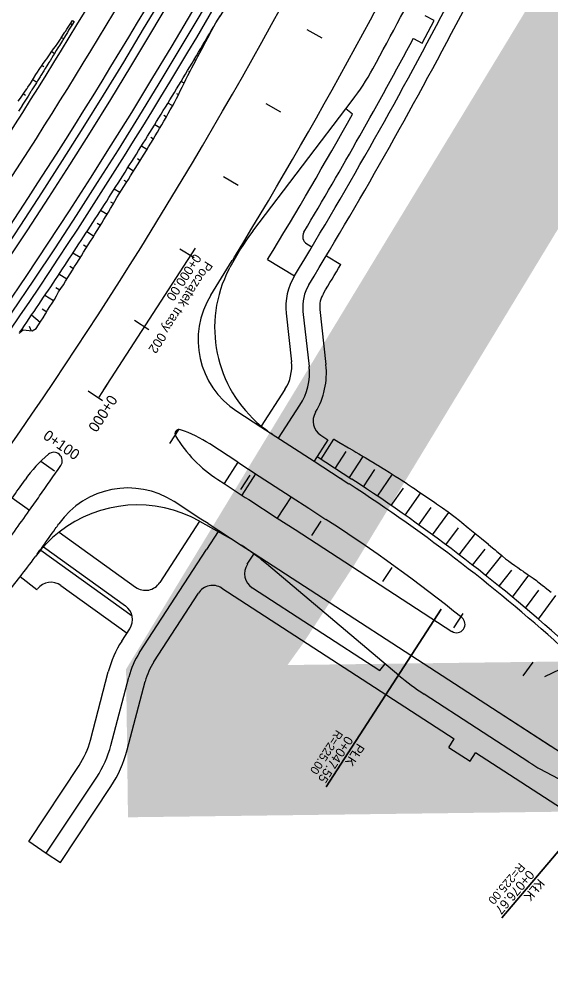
# Model space of a CAD drawing. Extents: x 6503541 to 6503743, y 5888004 to 5888145.
# Drawn here: x 6503687.09 to 6503688.597, y 5888085.781 to 5888088.473 of the extents above; entities that cross this region are included whole.
import ezdxf

# ---------------------------------------------------------------- set-up
doc = ezdxf.new("R2010")
doc.units = 0
doc.layers.add('12', color=7, linetype='Continuous')

msp = doc.modelspace()

# ---------------------------------------------------------------- linework, layer by layer
at = {"layer": '12'}
for p, q in [((6503688.2665, 5888088.4688), (6503688.2411, 5888088.4823)), ((6503687.6414, 5888088.4512), (6503687.6415, 5888088.4512)), ((6503687.648, 5888088.4625), (6503687.6478, 5888088.4626)), ((6503688.2327, 5888088.4052), (6503688.2665, 5888088.4688)), ((6503687.6243, 5888088.4195), (6503687.6229, 5888088.4203)), ((6503688.2073, 5888088.4187), (6503688.2327, 5888088.4052)), ((6503687.606, 5888088.3885), (6503687.6074, 5888088.3878)), ((6503687.5904, 5888088.356), (6503687.5861, 5888088.3583)), ((6503687.5707, 5888088.3257), (6503687.5739, 5888088.3241)), ((6503687.5578, 5888088.2918), (6503687.5489, 5888088.2963)), ((6503687.536, 5888088.2625), (6503687.5417, 5888088.2596)), ((6503687.9847, 5888088.2862), (6503687.9847, 5888088.2862)), ((6503687.5253, 5888088.2276), (6503687.5117, 5888088.235)), ((6503687.7524, 5888087.8721), (6503688.0339, 5888088.2422)), ((6503688.0352, 5888088.2042), (6503688.0161, 5888088.2187)), ((6503687.5002, 5888088.2005), (6503687.5074, 5888088.1964)), ((6503687.4893, 5888088.1652), (6503687.4743, 5888088.174)), ((6503687.4632, 5888088.1389), (6503687.4709, 5888088.1343)), ((6503687.4522, 5888088.1035), (6503687.4365, 5888088.1131)), ((6503687.4255, 5888088.0777), (6503687.4335, 5888088.0728)), ((6503687.4144, 5888088.0423), (6503687.3984, 5888088.0523)), ((6503687.3872, 5888088.0169), (6503687.3951, 5888088.0118)), ((6503687.3759, 5888087.9814), (6503687.3598, 5888087.9914)), ((6503687.3487, 5888087.9557), (6503687.3572, 5888087.9506)), ((6503687.3392, 5888087.9195), (6503687.3209, 5888087.9305)), ((6503687.3109, 5888087.8947), (6503687.3203, 5888087.8889)), ((6503687.3013, 5888087.8583), (6503687.2819, 5888087.8703)), ((6503687.2723, 5888087.8339), (6503687.2823, 5888087.8277)), ((6503687.9052, 5888087.8365), (6503687.92, 5888087.8275)), ((6503687.2632, 5888087.7972), (6503687.2426, 5888087.8101)), ((6503687.7943, 5888087.7915), (6503687.8702, 5888087.7454)), ((6503687.9608, 5888087.8027), (6503688.0018, 5888087.7778)), ((6503687.2254, 5888087.7359), (6503687.203, 5888087.7501)), ((6503687.2334, 5888087.7733), (6503687.2442, 5888087.7666)), ((6503687.6851, 5888087.7653), (6503687.6873, 5888087.7695)), ((6503687.1943, 5888087.7129), (6503687.2057, 5888087.7058)), ((6503687.1876, 5888087.6747), (6503687.1627, 5888087.6897)), ((6503687.1557, 5888087.6521), (6503687.1687, 5888087.6441)), ((6503687.8945, 5888087.645), (6503687.9119, 5888087.4887)), ((6503687.9422, 5888087.6503), (6503687.9596, 5888087.494)), ((6503687.1498, 5888087.6135), (6503687.1251, 5888087.6339)), ((6503687.8468, 5888087.6397), (6503687.8621, 5888087.5022)), ((6503687.1184, 5888087.6026), (6503687.1245, 5888087.5902)), ((6503687.0905, 5888087.583), (6503687.0908, 5888087.5827)), ((6503687.0918, 5888087.5846), (6503687.0917, 5888087.5848)), ((6503687.8435, 5888087.4237), (6503687.7763, 5888087.32)), ((6503687.8254, 5888087.2855), (6503687.8859, 5888087.3788)), ((6503687.7067, 5888087.3625), (6503687.7751, 5888087.3182)), ((6503687.7751, 5888087.3182), (6503687.9261, 5888087.2202)), ((6503687.945, 5888087.2938), (6503687.9653, 5888087.2807)), ((6503687.7098, 5888087.2175), (6503687.6302, 5888087.2691)), ((6503687.9653, 5888087.2807), (6503687.9261, 5888087.2202)), ((6503687.7098, 5888087.2175), (6503687.6707, 5888087.1571)), ((6503687.7098, 5888087.2175), (6503687.7702, 5888087.1783)), ((6503687.9261, 5888087.2202), (6503688.0249, 5888087.1562)), ((6503687.9346, 5888087.2333), (6503688.0334, 5888087.1693)), ((6503687.6533, 5888087.1683), (6503687.6707, 5888087.1571)), ((6503687.7702, 5888087.1783), (6503687.8609, 5888087.1196)), ((6503687.9969, 5888087.1744), (6503688.0015, 5888087.1714)), ((6503687.6707, 5888087.1571), (6503687.7311, 5888087.1179)), ((6503687.1192, 5888087.0803), (6503687.0703, 5888087.1155)), ((6503687.6054, 5888087.0563), (6503687.5292, 5888087.1058)), ((6503687.7311, 5888087.1179), (6503687.7411, 5888087.1114)), ((6503687.7411, 5888087.1114), (6503687.8217, 5888087.0591)), ((6503687.8609, 5888087.1196), (6503687.8217, 5888087.0591)), ((6503687.8609, 5888087.1196), (6503687.9112, 5888087.0869)), ((6503687.9112, 5888087.0869), (6503687.9596, 5888087.0555)), ((6503687.6013, 5888087.0508), (6503687.6914, 5888087.0006)), ((6503687.6254, 5888087.0434), (6503687.6054, 5888087.0563)), ((6503687.8217, 5888087.0591), (6503687.872, 5888087.0265)), ((6503687.6254, 5888087.0434), (6503687.7193, 5888086.9825)), ((6503687.872, 5888087.0265), (6503688.3166, 5888086.7382)), ((6503687.2037, 5888087.0195), (6503687.4203, 5888086.8635)), ((6503687.1589, 5888086.9778), (6503687.3915, 5888086.8104)), ((6503687.4316, 5888086.6781), (6503687.6207, 5888086.9698)), ((6503687.7194, 5888086.9825), (6503687.7565, 5888086.9584)), ((6503687.1519, 5888086.968), (6503687.4102, 5888086.7821)), ((6503687.7368, 5888086.9282), (6503687.7557, 5888086.9573)), ((6503687.7565, 5888086.9584), (6503688.4316, 5888086.5207)), ((6503688.1664, 5888086.6134), (6503687.7913, 5888086.9292)), ((6503687.1401, 5888086.8555), (6503687.0928, 5888086.8923)), ((6503687.2085, 5888086.8682), (6503687.3959, 5888086.7333)), ((6503687.751, 5888086.8619), (6503688.1123, 5888086.6276)), ((6503687.4719, 5888086.652), (6503687.5981, 5888086.8466)), ((6503687.6645, 5888086.8607), (6503688.3234, 5888086.4335)), ((6503687.3813, 5888086.7108), (6503687.4037, 5888086.7453)), ((6503688.1123, 5888086.6276), (6503688.1278, 5888086.6459)), ((6503687.2921, 5888086.43), (6503687.3428, 5888086.6236)), ((6503687.3501, 5888086.4148), (6503687.4009, 5888086.6084)), ((6503687.3966, 5888086.4026), (6503687.4473, 5888086.5962)), ((6503688.5345, 5888086.3678), (6503688.238, 5888086.5604)), ((6503688.4316, 5888086.5207), (6503688.5962, 5888086.414)), ((6503688.4316, 5888086.5207), (6503688.8048, 5888086.2787)), ((6503688.3078, 5888086.4094), (6503688.3234, 5888086.4335)), ((6503688.3078, 5888086.4094), (6503688.3681, 5888086.3702)), ((6503688.3681, 5888086.3702), (6503688.3837, 5888086.3942)), ((6503688.8019, 5888086.1227), (6503688.3837, 5888086.3942)), ((6503687.1172, 5888086.1428), (6503687.26, 5888086.3582)), ((6503687.1672, 5888086.1096), (6503687.31, 5888086.3251)), ((6503687.2072, 5888086.0831), (6503687.35, 5888086.2986)), ((6503687.1175, 5888086.1432), (6503687.1672, 5888086.1096)), ((6503687.1672, 5888086.1096), (6503687.2072, 5888086.0831))]:
    msp.add_line(p, q, dxfattribs=at)
for points in [[(6503687.648, 5888088.4625), (6503687.6546, 5888088.4727), (6503687.6612, 5888088.4828), (6503687.6677, 5888088.493), (6503687.6743, 5888088.5032), (6503687.6808, 5888088.5134), (6503687.687, 5888088.5238), (6503687.693, 5888088.5342), (6503687.6991, 5888088.5447), (6503687.7052, 5888088.5551), (6503687.7112, 5888088.5656), (6503687.717, 5888088.5762), (6503687.7226, 5888088.5869), (6503687.7283, 5888088.5976), (6503687.7339, 5888088.6083), (6503687.7395, 5888088.6191), (6503687.745, 5888088.6298), (6503687.7506, 5888088.6405)], [(6503687.0916, 5888087.5847), (6503687.0984, 5888087.5947), (6503687.1053, 5888087.6047), (6503687.112, 5888087.6147), (6503687.1188, 5888087.6247), (6503687.1256, 5888087.6347), (6503687.1324, 5888087.6447), (6503687.1392, 5888087.6547), (6503687.1459, 5888087.6647), (6503687.1527, 5888087.6748), (6503687.1594, 5888087.6848), (6503687.1661, 5888087.6948), (6503687.1729, 5888087.7049), (6503687.1796, 5888087.7149), (6503687.1863, 5888087.725), (6503687.193, 5888087.735), (6503687.1997, 5888087.7451), (6503687.2064, 5888087.7552), (6503687.213, 5888087.7653), (6503687.2197, 5888087.7753), (6503687.2264, 5888087.7854), (6503687.233, 5888087.7955), (6503687.2397, 5888087.8056), (6503687.2463, 5888087.8157), (6503687.2529, 5888087.8258), (6503687.2595, 5888087.8359), (6503687.2661, 5888087.8461), (6503687.2727, 5888087.8562), (6503687.2793, 5888087.8663), (6503687.2859, 5888087.8764), (6503687.2925, 5888087.8866), (6503687.2991, 5888087.8967), (6503687.3056, 5888087.9069), (6503687.3122, 5888087.917), (6503687.3187, 5888087.9272), (6503687.3253, 5888087.9374), (6503687.3318, 5888087.9475), (6503687.3383, 5888087.9577), (6503687.3448, 5888087.9679), (6503687.3514, 5888087.9781), (6503687.3579, 5888087.9883), (6503687.3643, 5888087.9985), (6503687.3708, 5888088.0087), (6503687.3773, 5888088.0189), (6503687.3838, 5888088.0291), (6503687.3902, 5888088.0393), (6503687.3967, 5888088.0495), (6503687.4031, 5888088.0598), (6503687.4095, 5888088.07), (6503687.416, 5888088.0802), (6503687.4224, 5888088.0905), (6503687.4288, 5888088.1007), (6503687.4352, 5888088.111), (6503687.4416, 5888088.1212), (6503687.448, 5888088.1315), (6503687.4543, 5888088.1418), (6503687.4607, 5888088.152), (6503687.4671, 5888088.1623), (6503687.4734, 5888088.1726), (6503687.4797, 5888088.1829), (6503687.4861, 5888088.1932), (6503687.4924, 5888088.2035), (6503687.4987, 5888088.2138), (6503687.505, 5888088.2241), (6503687.5113, 5888088.2344), (6503687.5176, 5888088.2447), (6503687.5239, 5888088.2551), (6503687.5302, 5888088.2654), (6503687.5365, 5888088.2757), (6503687.5427, 5888088.2861), (6503687.549, 5888088.2964), (6503687.5552, 5888088.3068), (6503687.5614, 5888088.3171), (6503687.5677, 5888088.3275), (6503687.5739, 5888088.3378), (6503687.5801, 5888088.3482), (6503687.5863, 5888088.3586), (6503687.5925, 5888088.369), (6503687.5987, 5888088.3794), (6503687.6048, 5888088.3897), (6503687.611, 5888088.4001), (6503687.6172, 5888088.4105), (6503687.6233, 5888088.4209), (6503687.6295, 5888088.4314), (6503687.6356, 5888088.4418), (6503687.6417, 5888088.4522), (6503687.6478, 5888088.4626), (6503687.654, 5888088.473), (6503687.6601, 5888088.4835)], [(6503687.0876, 5888088.2405), (6503687.0936, 5888088.2489), (6503687.1012, 5888088.2601), (6503687.1031, 5888088.2629), (6503687.1118, 5888088.2757), (6503687.1125, 5888088.2768), (6503687.1146, 5888088.2799), (6503687.1219, 5888088.2908), (6503687.1276, 5888088.3), (6503687.1307, 5888088.3052), (6503687.1377, 5888088.3164), (6503687.1397, 5888088.3193), (6503687.1403, 5888088.3202), (6503687.1492, 5888088.3333), (6503687.1537, 5888088.34), (6503687.1587, 5888088.3472), (6503687.1651, 5888088.3562), (6503687.1675, 5888088.3596), (6503687.1684, 5888088.361), (6503687.1782, 5888088.3747), (6503687.1813, 5888088.3791), (6503687.1879, 5888088.3885), (6503687.193, 5888088.3957), (6503687.1951, 5888088.3987), (6503687.1976, 5888088.4023), (6503687.2071, 5888088.4163), (6503687.2085, 5888088.4185), (6503687.2163, 5888088.4304), (6503687.2199, 5888088.4358), (6503687.2216, 5888088.4385), (6503687.2254, 5888088.4445), (6503687.2344, 5888088.4586), (6503687.2345, 5888088.4587), (6503687.2412, 5888088.4692)], [(6503687.2457, 5888088.4665), (6503687.2393, 5888088.4559), (6503687.2392, 5888088.4557), (6503687.2305, 5888088.4414), (6503687.2268, 5888088.4353), (6503687.2251, 5888088.4326), (6503687.2218, 5888088.4271), (6503687.2143, 5888088.4149), (6503687.213, 5888088.4127), (6503687.2042, 5888088.3983), (6503687.2019, 5888088.3945), (6503687.2, 5888088.3914), (6503687.1954, 5888088.3839), (6503687.1894, 5888088.3741), (6503687.1866, 5888088.3696), (6503687.1777, 5888088.3552), (6503687.1768, 5888088.3538), (6503687.1747, 5888088.3503), (6503687.1689, 5888088.3409), (6503687.1643, 5888088.3334), (6503687.16, 5888088.3266), (6503687.1517, 5888088.3131), (6503687.1511, 5888088.3123), (6503687.1493, 5888088.3092), (6503687.1422, 5888088.2979), (6503687.139, 5888088.2928), (6503687.1333, 5888088.2837), (6503687.1264, 5888088.2726), (6503687.1244, 5888088.2694), (6503687.1237, 5888088.2683), (6503687.1154, 5888088.2551), (6503687.1137, 5888088.2523), (6503687.1065, 5888088.2408), (6503687.1009, 5888088.2321), (6503687.098, 5888088.2274), (6503687.0975, 5888088.2266), (6503687.0885, 5888088.2123)], [(6503687.0918, 5888087.5846), (6503687.1011, 5888087.5929), (6503687.1269, 5888087.59), (6503687.1385, 5888087.5967), (6503687.1453, 5888087.6068), (6503687.152, 5888087.6168), (6503687.1585, 5888087.6271), (6503687.1647, 5888087.6375), (6503687.1709, 5888087.6479), (6503687.1772, 5888087.6583), (6503687.1837, 5888087.6685), (6503687.1901, 5888087.6788), (6503687.196, 5888087.6894), (6503687.2017, 5888087.7001), (6503687.2087, 5888087.71), (6503687.2156, 5888087.72), (6503687.2219, 5888087.7303), (6503687.2283, 5888087.7406), (6503687.2346, 5888087.751), (6503687.2409, 5888087.7613), (6503687.2472, 5888087.7717), (6503687.2536, 5888087.7819), (6503687.2601, 5888087.7922), (6503687.2665, 5888087.8024), (6503687.273, 5888087.8127), (6503687.2794, 5888087.823), (6503687.2858, 5888087.8332), (6503687.2922, 5888087.8435), (6503687.2986, 5888087.8538), (6503687.305, 5888087.8641), (6503687.3113, 5888087.8744), (6503687.3177, 5888087.8847), (6503687.3241, 5888087.895), (6503687.3304, 5888087.9053), (6503687.3367, 5888087.9156), (6503687.3432, 5888087.9259), (6503687.3495, 5888087.9362), (6503687.3552, 5888087.9469), (6503687.361, 5888087.9576), (6503687.3673, 5888087.9679), (6503687.3738, 5888087.9781), (6503687.3803, 5888087.9883), (6503687.3867, 5888087.9986), (6503687.3932, 5888088.0088), (6503687.3997, 5888088.019), (6503687.4062, 5888088.0292), (6503687.4126, 5888088.0395), (6503687.4191, 5888088.0497), (6503687.4255, 5888088.0599), (6503687.4319, 5888088.0702), (6503687.4383, 5888088.0805), (6503687.4446, 5888088.0909), (6503687.4508, 5888088.1012), (6503687.4571, 5888088.1115), (6503687.4634, 5888088.1219), (6503687.4697, 5888088.1322), (6503687.476, 5888088.1426), (6503687.4822, 5888088.1529), (6503687.4883, 5888088.1634), (6503687.4944, 5888088.1739), (6503687.5004, 5888088.1844), (6503687.5065, 5888088.1948), (6503687.5125, 5888088.2053), (6503687.5186, 5888088.2158), (6503687.5246, 5888088.2263), (6503687.5304, 5888088.237), (6503687.5358, 5888088.2478), (6503687.5413, 5888088.2587), (6503687.5467, 5888088.2695), (6503687.5521, 5888088.2804), (6503687.5575, 5888088.2912), (6503687.5629, 5888088.3021), (6503687.5684, 5888088.313), (6503687.5737, 5888088.3238), (6503687.5791, 5888088.3347), (6503687.5848, 5888088.3454), (6503687.5905, 5888088.3561), (6503687.5962, 5888088.3668), (6503687.6019, 5888088.3774), (6503687.6076, 5888088.3881), (6503687.6133, 5888088.3988), (6503687.619, 5888088.4095), (6503687.6246, 5888088.4202), (6503687.6303, 5888088.4309), (6503687.6361, 5888088.4415), (6503687.642, 5888088.452), (6503687.648, 5888088.4625)], [(6503687.236, 5888088.461), (6503687.2406, 5888088.4582)], [(6503687.2412, 5888088.4692), (6503687.2457, 5888088.4665)], [(6503687.9486, 5888088.4196), (6503687.9065, 5888088.4426)], [(6503687.2099, 5888088.4207), (6503687.2128, 5888088.4189)], [(6503687.1827, 5888088.3811), (6503687.1906, 5888088.3762)], [(6503687.155, 5888088.3418), (6503687.1602, 5888088.3386)], [(6503687.1286, 5888088.3018), (6503687.1401, 5888088.2946)], [(6503687.1023, 5888088.2617), (6503687.1085, 5888088.2578)], [(6503687.8315, 5888088.2097), (6503687.7898, 5888088.2334)], [(6503687.7106, 5888088.0018), (6503687.6694, 5888088.0263)], [(6503687.3288, 5888087.4216), (6503687.4593, 5888087.623), (6503687.5899, 5888087.8244)], [(6503687.5861, 5888087.7962), (6503687.5452, 5888087.8214)], [(6503687.4579, 5888087.5928), (6503687.4175, 5888087.6187)], [(6503687.3418, 5888087.4417), (6503687.3157, 5888087.4015)], [(6503687.326, 5888087.3917), (6503687.2861, 5888087.4184)], [(6503687.5171, 5888087.2709), (6503687.5432, 5888087.3112)], [(6503687.9459, 5888087.226), (6503687.9823, 5888087.2827)], [(6503687.9823, 5888087.2827), (6503687.9827, 5888087.2831), (6503687.9841, 5888087.2823), (6503688.0012, 5888087.2718), (6503688.0032, 5888087.2706), (6503688.0184, 5888087.2613), (6503688.0237, 5888087.2582), (6503688.0358, 5888087.2512), (6503688.0445, 5888087.2461), (6503688.0532, 5888087.2411), (6503688.0652, 5888087.234), (6503688.0705, 5888087.2308), (6503688.0858, 5888087.2217), (6503688.0878, 5888087.2205), (6503688.105, 5888087.2101), (6503688.1064, 5888087.2092), (6503688.1221, 5888087.1996), (6503688.1268, 5888087.1967), (6503688.1392, 5888087.189), (6503688.1472, 5888087.184), (6503688.1562, 5888087.1783), (6503688.1674, 5888087.171), (6503688.1731, 5888087.1673), (6503688.1875, 5888087.1579), (6503688.1899, 5888087.1563), (6503688.2066, 5888087.1451), (6503688.2075, 5888087.1446), (6503688.2233, 5888087.1339), (6503688.2273, 5888087.1311), (6503688.2399, 5888087.1225), (6503688.2471, 5888087.1175), (6503688.2565, 5888087.1111), (6503688.267, 5888087.104), (6503688.2731, 5888087.0998), (6503688.2867, 5888087.0904), (6503688.2896, 5888087.0884), (6503688.3061, 5888087.0768), (6503688.3064, 5888087.0766), (6503688.3221, 5888087.0645), (6503688.3255, 5888087.0619), (6503688.3379, 5888087.052), (6503688.3443, 5888087.0468), (6503688.3631, 5888087.0317), (6503688.3818, 5888087.0164), (6503688.4005, 5888087.0011), (6503688.4107, 5888086.9926), (6503688.419, 5888086.9857), (6503688.4194, 5888086.9854), (6503688.4273, 5888086.9788), (6503688.4356, 5888086.9718), (6503688.4387, 5888086.9692), (6503688.4438, 5888086.9649), (6503688.4521, 5888086.9579), (6503688.458, 5888086.953), (6503688.4603, 5888086.951), (6503688.4686, 5888086.9441), (6503688.4771, 5888086.9377), (6503688.4776, 5888086.9374), (6503688.4858, 5888086.9314), (6503688.4945, 5888086.9252), (6503688.4979, 5888086.9228), (6503688.5032, 5888086.919), (6503688.512, 5888086.9129), (6503688.5183, 5888086.9085), (6503688.5207, 5888086.9068), (6503688.5295, 5888086.9006), (6503688.5383, 5888086.8945), (6503688.5388, 5888086.8942), (6503688.5471, 5888086.8885), (6503688.5559, 5888086.8824), (6503688.5592, 5888086.8798), (6503688.5643, 5888086.8757), (6503688.5727, 5888086.8691), (6503688.5788, 5888086.8643), (6503688.5811, 5888086.8625), (6503688.5896, 5888086.8559), (6503688.598, 5888086.8494)], [(6503687.986, 5888087.2), (6503688.0169, 5888087.2477)], [(6503687.1512, 5888087.2204), (6503687.1907, 5888087.193)], [(6503688.0261, 5888087.174), (6503688.0653, 5888087.2339)], [(6503687.7602, 5888087.1848), (6503687.721, 5888087.1244)], [(6503688.0659, 5888087.148), (6503688.0986, 5888087.1968)], [(6503687.7185, 5888087.1403), (6503687.7446, 5888087.1806)], [(6503688.1055, 5888087.1216), (6503688.1478, 5888087.1836)], [(6503688.1448, 5888087.0948), (6503688.179, 5888087.1439)], [(6503688.1839, 5888087.0677), (6503688.2285, 5888087.1303)], [(6503688.2227, 5888087.0401), (6503688.2581, 5888087.0889)], [(6503687.6017, 5888087.0506), (6503687.4887, 5888086.8764)], [(6503687.9199, 5888087.0098), (6503687.946, 5888087.0501)], [(6503688.2612, 5888087.0121), (6503688.3081, 5888087.0754)], [(6503688.2994, 5888086.9838), (6503688.3355, 5888087.0315)], [(6503687.6542, 5888087.0213), (6503687.6207, 5888086.9698)], [(6503688.3374, 5888086.9551), (6503688.3836, 5888087.015)], [(6503688.3751, 5888086.926), (6503688.4109, 5888086.9715)], [(6503688.4127, 5888086.8963), (6503688.4576, 5888086.9533)], [(6503688.1212, 5888086.8792), (6503688.1474, 5888086.9195)], [(6503688.4504, 5888086.866), (6503688.486, 5888086.9119)], [(6503688.4879, 5888086.8353), (6503688.5347, 5888086.897)], [(6503688.525, 5888086.8041), (6503688.563, 5888086.8551)], [(6503688.562, 5888086.7725), (6503688.6108, 5888086.8395)], [(6503688.2864, 5888086.8008), (6503687.96, 5888086.2973), (6503688.2864, 5888086.8008)], [(6503688.3222, 5888086.7485), (6503688.3488, 5888086.7885)], [(6503688.58, 5888086.6104), (6503688.8169, 5888086.7234)], [(6503688.5183, 5888086.612), (6503688.5466, 5888086.6508)], [(6503688.8465, 5888086.3838), (6503688.4579, 5888085.9267), (6503688.8465, 5888086.3838)]]:
    msp.add_lwpolyline(points, dxfattribs=at)
for centre, radius, start, end in [((6503674.6145, 5888096.105), 14.7732, 325.59328, 335.91738), ((6503674.6145, 5888096.105), 14.8452, 325.59328, 335.91738), ((6503674.6145, 5888096.105), 14.9172, 323.94916, 335.91738), ((6503674.6145, 5888096.105), 14.9412, 282.48188, 335.91738), ((6503674.6145, 5888096.105), 14.9652, 282.48188, 335.91738), ((6503674.6145, 5888096.105), 15.0348, 282.48188, 335.91738), ((6503674.6145, 5888096.105), 15.0588, 282.48188, 335.91738), ((6503674.6145, 5888096.105), 15.0828, 323.95246, 335.91738), ((6503676.1325, 5888094.874), 13.56, 328.57082, 334.69463), ((6503676.1325, 5888094.874), 13.32, 324.65355, 332.4155), ((6503676.1325, 5888094.874), 13.632, 331.32382, 332.71862), ((6503676.1325, 5888094.874), 13.7328, 328.72878, 332.48698), ((6503676.1325, 5888094.874), 13.7808, 328.72878, 332.48698), ((6503676.1325, 5888094.874), 13.692, 329.23006, 331.87069), ((6503687.4608, 5888088.678), 0.72, 322.7436, 331.3238), ((6503676.1325, 5888094.874), 13.644, 328.72878, 330.73543), ((6503688.3255, 5888087.4362), 0.72, 142.7436, 152.4248), ((6503687.9177, 5888087.857), 0.024, 149.2301, 238.7288), ((6503676.1325, 5888094.874), 13.56, 328.01351, 328.49919), ((6503676.1325, 5888094.874), 13.56, 328.49919, 328.57082), ((6503676.1325, 5888094.874), 13.8288, 328.72878, 329.12653), ((6503688.0042, 5888087.5987), 0.36, 152.4248, 230.7262), ((6503688.0138, 5888087.6582), 0.168, 148.7288, 186.3408), ((6503688.0138, 5888087.6582), 0.12, 148.7288, 186.3408), ((6503687.8373, 5888087.5639), 0.24, 148.0135, 237.043), ((6503688.0138, 5888087.6582), 0.072, 148.7288, 186.3408), ((6503687.7428, 5888087.489), 0.12, 327.043, 6.3408), ((6503687.7449, 5888087.4702), 0.168, 327.043, 6.3408), ((6503687.7449, 5888087.4702), 0.216, 328.9706, 6.3408), ((6503687.9712, 5888087.3341), 0.048, 148.9706, 237.043), ((6503688.0042, 5888087.5987), 0.36, 230.7262, 237.043), ((6503687.5438, 5888087.2982), 0.012, 70.7743, 211.1418), ((6503687.8622, 5888087.4905), 0.384, 211.1418, 237.0438), ((6503687.4213, 5888086.9469), 0.384, 57.043, 70.7743), ((6503687.4213, 5888086.9469), 0.384, 130.2806, 144.9231), ((6503687.1885, 5888087.2215), 0.024, 325.3109, 130.2806), ((6503676.1325, 5888094.874), 13.47, 324.86469, 325.31085), ((6503676.1325, 5888094.874), 13.41, 324.65084, 324.92307), ((6503685.325, 5888083.0431), 4.92, 56.9724, 57.043), ((6503685.4137, 5888083.1286), 4.8156, 47.7221, 57.043), ((6503687.3986, 5888086.9044), 0.24, 57.043, 144.7246), ((6503685.4137, 5888083.1286), 4.8, 47.7221, 57.043), ((6503676.1325, 5888094.874), 13.47, 324.64905, 324.86469), ((6503676.1325, 5888094.874), 13.47, 324.02992, 324.64905), ((6503687.426, 5888086.7364), 0.36, 60.8571, 128.1461), ((6503685.4137, 5888083.1286), 4.68, 51.223, 57.043), ((6503676.1325, 5888094.874), 13.56, 324.39288, 324.64954), ((6503676.1325, 5888094.874), 13.56, 324.64954, 324.72455), ((6503687.426, 5888086.7364), 0.36, 128.1461, 143.8059), ((6503676.1325, 5888094.874), 13.56, 324.2759, 324.39288), ((6503687.3277, 5888086.3783), 0.72, 53.5264, 57.043), ((6503685.1986, 5888088.3662), 2.4, 322.112, 323.8059), ((6503687.3277, 5888086.3783), 0.72, 49.9092, 53.5264), ((6503687.7771, 5888086.9021), 0.048, 147.043, 237.043), ((6503685.1986, 5888088.3662), 2.4, 318.9467, 322.112), ((6503687.1805, 5888086.8292), 0.048, 54.2501, 142.2028), ((6503687.4484, 5888086.9025), 0.048, 234.2501, 327.043), ((6503687.6383, 5888086.8205), 0.048, 57.043, 147.043), ((6503685.1702, 5888088.3883), 2.496, 322.112, 322.2028), ((6503687.3634, 5888086.7714), 0.048, 327.043, 54.2501), ((6503688.3297, 5888086.7584), 0.024, 237.043, 51.223), ((6503687.633, 5888086.5476), 0.3, 147.043, 165.319), ((6503687.633, 5888086.5476), 0.24, 147.043, 165.319), ((6503687.633, 5888086.5476), 0.192, 147.043, 165.319), ((6503688.6301, 5888087.1642), 0.72, 229.9092, 237.0011), ((6503687.0599, 5888086.4908), 0.24, 326.4655, 345.319), ((6503687.0599, 5888086.4908), 0.3, 326.4655, 345.319), ((6503687.0599, 5888086.4908), 0.348, 326.4655, 345.319), ((6503688.9266, 5888086.9717), 0.72, 237.0011, 249.9727)]:
    msp.add_arc(centre, radius, start, end, dxfattribs=at)

# ---------------------------------------------------------------- texts
for s, height, rotation, p in [('14', 4.22297, 0.7393, (6503684.141, 5888085.213)), ('0+000.00', 0.0264, 237.043, (6503687.5864, 5888087.8103)), ('Początek trasy 002', 0.0264, 237.043, (6503687.6186, 5888087.7894)), ('0+000', 0.03, 237.043, (6503687.3455, 5888087.4109)), ('0+100', 0.03, 325.2163, (6503687.1556, 5888087.2862)), ('R=225.00', 0.024, 237.043, (6503687.9895, 5888086.4606)), ('0+047.55', 0.0264, 237.043, (6503688.0164, 5888086.4439)), ('PŁK', 0.0264, 237.043, (6503688.0486, 5888086.423)), ('R=225.00', 0.024, 229.6289, (6503688.508, 5888086.084)), ('0+076.67', 0.0264, 229.6289, (6503688.5327, 5888086.0638)), ('KŁK', 0.0264, 229.6289, (6503688.562, 5888086.0389))]:
    msp.add_text(s, height=height, rotation=rotation, dxfattribs=at).set_placement(p)

doc.saveas('drawing.dxf')
